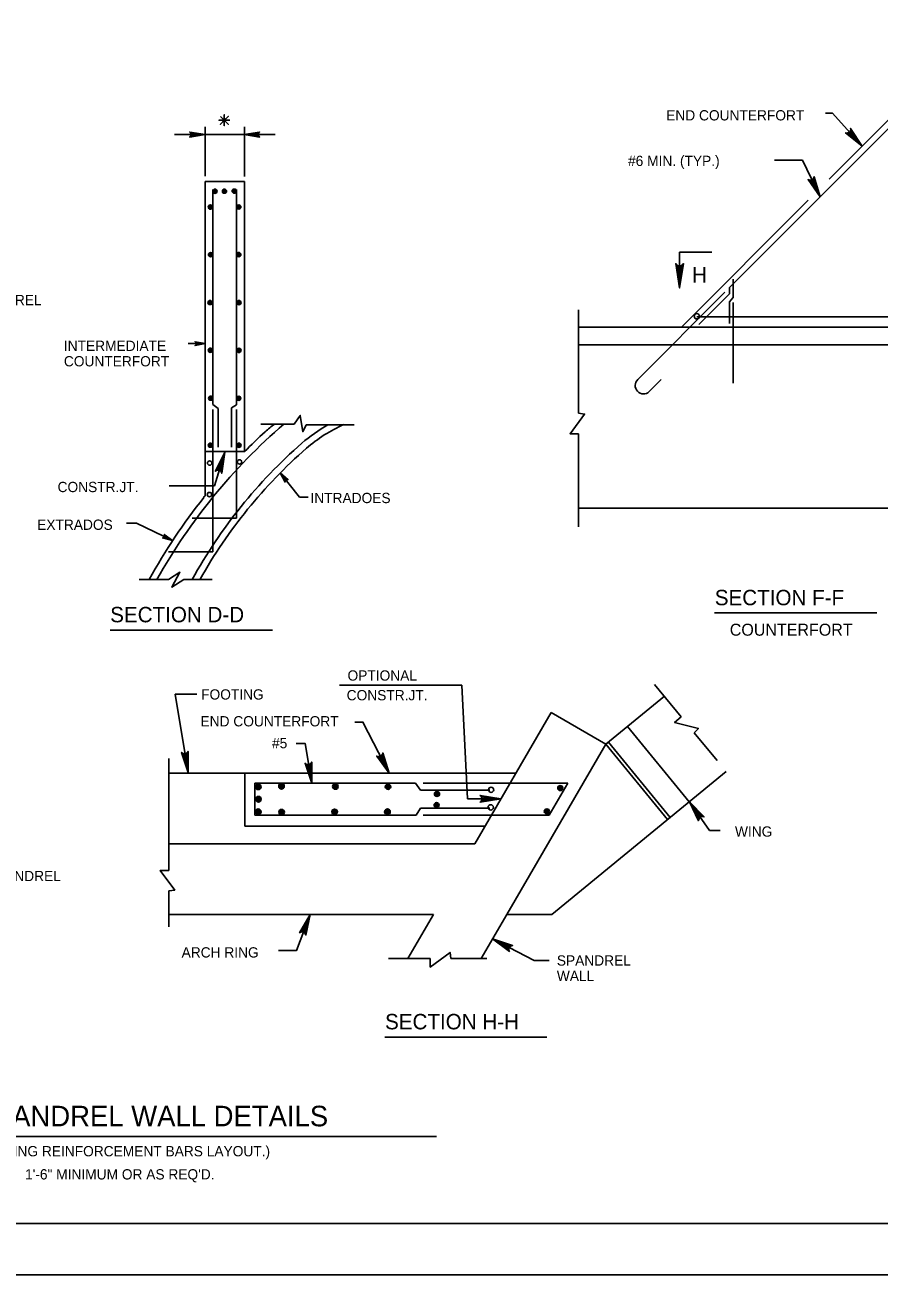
# Model space of a CAD drawing. Extents: x 639028 to 639883, y 298843 to 300031.
# Drawn here: x 639347.3 to 639596.7, y 298843.1 to 299207.9 of the extents above; entities that cross this region are included whole.
import ezdxf

# ---------------------------------------------------------------- set-up
doc = ezdxf.new("R2010")
doc.units = 0
for name, color, linetype in [('2', 7, 'Continuous'), ('52', 7, 'Continuous'), ('53', 7, 'Continuous'), ('PLT-BNDY', 7, 'Continuous')]:
    doc.layers.add(name, color=color, linetype=linetype)

msp = doc.modelspace()

# ---------------------------------------------------------------- linework, layer by layer
at = {"layer": '2'}
for p, q in [((639626.2, 299204.43), (639553.07, 299131.3)), ((639622.06, 299202.83), (639582.15, 299162.92)), ((639405.48, 299180.1), (639405.48, 299180.1)), ((639399.9, 299163.83), (639399.9, 299178.2)), ((639411.4, 299163.7), (639411.4, 299178.2)), ((639412.4, 299175.95), (639390.97, 299175.95)), ((639420.3, 299175.95), (639411.4, 299175.95)), ((639399.9, 299162.2), (639399.9, 299070.45)), ((639399.9, 299162.2), (639411.4, 299162.2)), ((639411.4, 299162.2), (639411.4, 299083.45)), ((639402.15, 299159.95), (639402.15, 299097.2)), ((639409.03, 299159.95), (639409.03, 299097.08)), ((639576.04, 299156.81), (639538.98, 299119.76)), ((639538.46, 299141.66), (639538.46, 299131.16)), ((639538.46, 299141.66), (639547.84, 299141.66)), ((639554.13, 299133.73), (639554.13, 299128.26)), ((639551.71, 299129.94), (639526.25, 299104.48)), ((639553.03, 299129.45), (639544.06, 299120.48)), ((639553.03, 299129.45), (639553.07, 299131.3)), ((639553.99, 299128.26), (639552.99, 299127.13)), ((639552.99, 299127.13), (639552.99, 299120.76)), ((639554.13, 299126.95), (639554.13, 299103.38)), ((639508.95, 299124.77), (639508.95, 299094.62)), ((639611.56, 299122.77), (639543.53, 299122.77)), ((639508.96, 299119.76), (639635.26, 299119.76)), ((639508.96, 299114.57), (639635.26, 299114.57)), ((639529.61, 299100.91), (639533.11, 299104.41)), ((639403.65, 299095.95), (639402.15, 299097.2)), ((639402.15, 299095.7), (639402.15, 299054.12)), ((639403.65, 299095.95), (639403.65, 299084.7)), ((639407.53, 299096.2), (639409.03, 299097.08)), ((639407.53, 299096.2), (639407.53, 299084.7)), ((639409.03, 299095.7), (639409.03, 299063.94)), ((639416.15, 299091.45), (639425.9, 299091.45)), ((639429.4, 299091.2), (639443.4, 299091.2)), ((639508.95, 299088.62), (639508.95, 299061.46)), ((639411.4, 299083.45), (639399.9, 299083.45)), ((639405.65, 299083.2), (639402.59, 299073.45)), ((639402.59, 299073.45), (639389.4, 299073.45)), ((639399.4, 299070.08), (639399.9, 299070.45)), ((639508.96, 299066.93), (639635.26, 299066.93)), ((639396.06, 299063.94), (639409.03, 299063.94)), ((639389.22, 299054.12), (639402.15, 299054.12)), ((639380.65, 299046.08), (639389.15, 299046.08)), ((639393.65, 299046.08), (639401.9, 299046.08)), ((639538.94, 299005.97), (639531.17, 299015.44)), ((639391.14, 299012.62), (639397.43, 299012.62)), ((639474.85, 299015.23), (639439.1, 299015.23)), ((639476.54, 298982.08), (639474.85, 299015.23)), ((639516.92, 298997.97), (639534.01, 299011.98)), ((639500.94, 299007.21), (639478.62, 298968.94)), ((639500.97, 299007.27), (639516.92, 298997.97)), ((639523.23, 299003.14), (639541.24, 298981.17)), ((639549.4, 298993.21), (639542.74, 299001.33)), ((639516.92, 298997.97), (639487.96, 298948.31)), ((639516.92, 298997.97), (639534.93, 298975.99)), ((639517.66, 298998.58), (639535.67, 298976.6)), ((639389.26, 298961.17), (639389.26, 298993.81)), ((639501.15, 298948.31), (639552.02, 298990)), ((639389.26, 298989.59), (639490.67, 298989.59)), ((639411.44, 298989.59), (639411.44, 298974.09)), ((639414.44, 298986.59), (639414.44, 298977.34)), ((639414.44, 298986.59), (639461.31, 298986.59)), ((639462.81, 298984.59), (639461.31, 298986.59)), ((639463.52, 298986.59), (639505.79, 298986.59)), ((639505.79, 298986.59), (639500.4, 298977.34)), ((639462.81, 298984.59), (639483.03, 298984.59)), ((639462.81, 298979.34), (639461.56, 298977.34)), ((639462.81, 298979.34), (639483.03, 298979.34)), ((639476.54, 298982.08), (639486.29, 298982.08)), ((639414.44, 298977.34), (639420.94, 298977.34)), ((639414.44, 298977.34), (639461.56, 298977.34)), ((639463.52, 298977.34), (639500.4, 298977.34)), ((639481.63, 298974.09), (639411.44, 298974.09)), ((639420.94, 298974.09), (639411.44, 298974.09)), ((639478.62, 298968.94), (639389.26, 298968.94)), ((639389.26, 298944.67), (639389.26, 298955.17)), ((639466.6, 298948.31), (639389.26, 298948.31)), ((639466.6, 298948.31), (639459.1, 298935.46)), ((639487.96, 298948.31), (639480.47, 298935.46)), ((639501.15, 298948.31), (639487.96, 298948.31)), ((639465.65, 298935.46), (639453.4, 298935.46)), ((639482.15, 298935.46), (639471.65, 298935.46)), ((639853.74, 298858.08), (639067.74, 298858.08))]:
    msp.add_line(p, q, dxfattribs=at)
for points in [[(639407.08, 299180.1), (639403.88, 299180.1), (639405.48, 299180.1), (639405.48, 299178.5), (639405.48, 299181.7), (639405.48, 299180.1), (639406.62, 299181.23), (639404.35, 299178.96), (639405.48, 299180.1), (639406.62, 299178.96), (639404.35, 299181.23)], [(639395.61, 299176.47), (639395.79, 299176.16), (639399.86, 299175.94), (639395.61, 299176.47), (639395.4, 299176.66), (639399.86, 299175.94), (639395.79, 299175.74), (639395.63, 299175.44), (639399.86, 299175.94), (639395.4, 299175.21), (639395.63, 299175.44)], [(639415.57, 299176.47), (639415.39, 299176.16), (639411.32, 299175.94), (639415.57, 299176.47), (639415.78, 299176.66), (639411.32, 299175.94), (639415.39, 299175.74), (639415.55, 299175.44), (639411.32, 299175.94), (639415.78, 299175.21), (639415.55, 299175.44)], [(639539.34, 299137.91), (639538.84, 299137.66), (639538.46, 299131.16), (639539.34, 299137.91), (639539.59, 299138.29), (639538.46, 299131.16), (639538.09, 299137.66), (639537.59, 299137.91), (639538.46, 299131.16), (639537.34, 299138.29), (639537.59, 299137.91)], [(639425.9, 299091.45), (639427.65, 299093.95), (639428.4, 299089.2), (639429.4, 299091.2)], [(639508.95, 299094.62), (639510.7, 299094.37), (639506.45, 299088.62), (639508.95, 299088.62)], [(639389.15, 299046.08), (639392.53, 299048.2), (639390.15, 299043.83), (639393.65, 299046.08)], [(639542.74, 299001.33), (639543.94, 299002.63), (639537, 299004.38), (639538.94, 299005.97)], [(639389.26, 298955.17), (639391.01, 298955.42), (639386.76, 298961.17), (639389.26, 298961.17)], [(639471.65, 298935.46), (639471.4, 298937.21), (639465.65, 298932.96), (639465.65, 298935.46)]]:
    msp.add_lwpolyline(points, dxfattribs=at)
for centre, radius in [((639402.75, 299159.4), 0.619), ((639402.75, 299159.39), 0.501), ((639402.75, 299159.39), 0.395), ((639402.75, 299159.38), 0.277), ((639402.75, 299159.4), 0.151), ((639402.76, 299159.39), 0.0427), ((639405.53, 299159.41), 0.619), ((639405.53, 299159.4), 0.501), ((639405.53, 299159.4), 0.395), ((639405.53, 299159.39), 0.277), ((639405.53, 299159.41), 0.151), ((639405.54, 299159.4), 0.0427), ((639408.39, 299159.43), 0.619), ((639408.39, 299159.43), 0.501), ((639408.39, 299159.43), 0.395), ((639408.39, 299159.41), 0.277), ((639408.39, 299159.44), 0.151), ((639408.4, 299159.43), 0.0427), ((639401.4, 299154.78), 0.619), ((639401.4, 299154.77), 0.501), ((639401.4, 299154.77), 0.395), ((639401.4, 299154.76), 0.277), ((639401.4, 299154.79), 0.151), ((639401.41, 299154.77), 0.0427), ((639409.69, 299154.81), 0.619), ((639409.7, 299154.8), 0.501), ((639409.7, 299154.8), 0.395), ((639409.7, 299154.79), 0.277), ((639409.7, 299154.81), 0.151), ((639409.71, 299154.8), 0.0427), ((639401.45, 299140.88), 0.619), ((639401.45, 299140.87), 0.501), ((639401.45, 299140.87), 0.395), ((639401.45, 299140.86), 0.277), ((639401.45, 299140.88), 0.151), ((639401.46, 299140.87), 0.0427), ((639409.69, 299140.91), 0.619), ((639409.7, 299140.9), 0.501), ((639409.7, 299140.9), 0.395), ((639409.7, 299140.89), 0.277), ((639409.7, 299140.91), 0.151), ((639409.71, 299140.9), 0.0427), ((639401.32, 299126.92), 0.619), ((639401.33, 299126.91), 0.501), ((639401.33, 299126.91), 0.395), ((639401.33, 299126.9), 0.277), ((639401.33, 299126.92), 0.151), ((639401.34, 299126.91), 0.0427), ((639409.74, 299126.89), 0.619), ((639409.74, 299126.88), 0.501), ((639409.74, 299126.88), 0.395), ((639409.74, 299126.87), 0.277), ((639409.74, 299126.89), 0.151), ((639409.75, 299126.88), 0.0427), ((639401.39, 299112.99), 0.619), ((639401.39, 299112.98), 0.501), ((639401.39, 299112.98), 0.395), ((639401.39, 299112.97), 0.277), ((639401.39, 299112.99), 0.151), ((639401.4, 299112.98), 0.0427), ((639409.74, 299112.95), 0.619), ((639409.74, 299112.94), 0.501), ((639409.74, 299112.94), 0.395), ((639409.74, 299112.93), 0.277), ((639409.74, 299112.96), 0.151), ((639409.75, 299112.94), 0.0427), ((639401.48, 299098.99), 0.619), ((639401.48, 299098.98), 0.501), ((639401.48, 299098.98), 0.395), ((639409.68, 299098.96), 0.619), ((639409.68, 299098.95), 0.501), ((639409.68, 299098.95), 0.395), ((639401.48, 299098.97), 0.277), ((639401.48, 299098.99), 0.151), ((639401.49, 299098.98), 0.0427), ((639409.68, 299098.94), 0.277), ((639409.68, 299098.96), 0.151), ((639409.69, 299098.95), 0.0427), ((639401.42, 299085.28), 0.619), ((639401.42, 299085.27), 0.501), ((639401.42, 299085.27), 0.395), ((639401.42, 299085.26), 0.277), ((639401.42, 299085.28), 0.151), ((639401.43, 299085.27), 0.0427), ((639409.77, 299085.25), 0.619), ((639409.77, 299085.24), 0.501), ((639409.77, 299085.24), 0.395), ((639409.77, 299085.23), 0.277), ((639409.77, 299085.25), 0.151), ((639409.79, 299085.24), 0.0427), ((639415.39, 298985.56), 0.825), ((639415.39, 298985.57), 0.668), ((639422.18, 298985.71), 0.825), ((639422.18, 298985.72), 0.668), ((639422.18, 298985.72), 0.527), ((639437.91, 298985.66), 0.825), ((639437.91, 298985.67), 0.668), ((639453.29, 298985.61), 0.825), ((639453.3, 298985.62), 0.668), ((639415.42, 298981.94), 0.825), ((639415.43, 298981.95), 0.668), ((639415.39, 298985.57), 0.527), ((639415.39, 298985.59), 0.37), ((639415.39, 298985.56), 0.202), ((639415.41, 298985.57), 0.0569), ((639422.18, 298985.73), 0.37), ((639422.18, 298985.7), 0.202), ((639422.2, 298985.72), 0.0569), ((639437.91, 298985.67), 0.527), ((639437.91, 298985.69), 0.37), ((639437.91, 298985.66), 0.202), ((639437.93, 298985.67), 0.0569), ((639453.3, 298985.62), 0.527), ((639453.3, 298985.63), 0.37), ((639453.3, 298985.61), 0.202), ((639453.31, 298985.62), 0.0569), ((639467.6, 298983.5), 0.75), ((639467.6, 298983.5), 0.563), ((639467.6, 298983.5), 0.375), ((639467.6, 298983.5), 0.188), ((639503.6, 298985.2), 0.75), ((639503.6, 298985.2), 0.563), ((639503.6, 298985.2), 0.375), ((639503.6, 298985.2), 0.188), ((639415.41, 298978.3), 0.825), ((639415.41, 298978.31), 0.668), ((639415.43, 298981.95), 0.527), ((639415.43, 298981.96), 0.37), ((639415.43, 298981.93), 0.202), ((639415.44, 298981.95), 0.0569), ((639422.23, 298978.16), 0.825), ((639437.71, 298978.22), 0.825), ((639453.14, 298978.31), 0.825), ((639453.15, 298978.33), 0.668), ((639467.48, 298980.21), 0.75), ((639467.48, 298980.21), 0.563), ((639467.48, 298980.21), 0.375), ((639467.48, 298980.21), 0.188), ((639499.7, 298978.38), 0.75), ((639415.41, 298978.31), 0.527), ((639415.41, 298978.32), 0.37), ((639415.41, 298978.3), 0.202), ((639415.42, 298978.31), 0.0569), ((639422.23, 298978.18), 0.668), ((639422.23, 298978.18), 0.527), ((639422.23, 298978.19), 0.37), ((639422.23, 298978.16), 0.202), ((639422.25, 298978.18), 0.0569), ((639437.72, 298978.23), 0.668), ((639437.72, 298978.23), 0.527), ((639437.72, 298978.24), 0.37), ((639437.72, 298978.21), 0.202), ((639437.73, 298978.23), 0.0569), ((639453.15, 298978.33), 0.527), ((639453.15, 298978.34), 0.37), ((639453.15, 298978.31), 0.202), ((639453.16, 298978.33), 0.0569), ((639499.7, 298978.38), 0.563), ((639499.7, 298978.38), 0.375), ((639499.7, 298978.38), 0.188)]:
    msp.add_circle(centre, radius, dxfattribs=at)
for centre, radius, start, end in [((639527.93, 299102.69), 2.45, 133.18, 313.18), ((639533.15, 298963.44), 168.95, 130.7372, 150.7163), ((639533.15, 298963.44), 170.93, 132.6358, 135.4203), ((639459.59, 299039.81), 64.97, 127.397, 130.5294), ((639459.59, 299049.09), 48.39, 119.5171, 130.5182), ((639459.59, 299049.09), 46.41, 114.388, 130.5182), ((639525.76, 298974.41), 148.16, 131.215, 151.0716), ((639525.76, 298974.41), 146.18, 131.215, 150.6112), ((639533.15, 298963.44), 170.93, 141.4339, 151.0783)]:
    msp.add_arc(centre, radius, start, end, dxfattribs=at)
at = {"layer": '52'}
msp.add_line((639394.94, 298989.75), (639391.14, 299012.62), dxfattribs=at)
for points in [[(639591.74, 299172.52), (639583.14, 299182.17), (639581.04, 299182.17)], [(639588.43, 299177.33), (639588.26, 299176.89), (639591.74, 299172.52), (639588.43, 299177.33), (639588.42, 299177.72), (639591.74, 299172.52), (639587.82, 299176.5), (639587.38, 299176.38), (639591.74, 299172.52), (639586.96, 299176.43), (639587.38, 299176.38)], [(639579.49, 299157.72), (639574.36, 299168.46), (639566.19, 299168.46)], [(639577.65, 299163.27), (639577.36, 299162.89), (639579.49, 299157.72), (639577.65, 299163.27), (639577.75, 299163.64), (639579.49, 299157.72), (639576.84, 299162.63), (639576.37, 299162.64), (639579.49, 299157.72), (639575.99, 299162.8), (639576.37, 299162.64)], [(639399.9, 299114.91), (639394.88, 299114.91)], [(639399.9, 299114.91), (639396.92, 299114.35), (639397.04, 299114.43), (639397.15, 299114.51), (639397.21, 299114.61), (639397.27, 299114.71), (639397.29, 299114.81), (639397.3, 299114.91), (639397.29, 299115.01), (639397.27, 299115.11), (639397.21, 299115.21), (639397.15, 299115.31), (639397.04, 299115.39), (639396.92, 299115.47), (639399.9, 299114.91), (639397.04, 299115.39), (639397.15, 299115.31), (639399.9, 299114.91), (639397.21, 299115.21), (639397.27, 299115.11), (639399.9, 299114.91), (639397.29, 299115.01), (639397.3, 299114.91), (639399.9, 299114.91), (639397.29, 299114.81), (639397.27, 299114.71), (639399.9, 299114.91), (639397.21, 299114.61), (639397.15, 299114.51), (639399.9, 299114.91), (639397.04, 299114.43)], [(639403.22, 299077.89), (639403.69, 299077.97), (639405.65, 299083.2), (639403.22, 299077.89), (639402.89, 299077.68), (639405.65, 299083.2), (639404.25, 299077.8), (639404.58, 299077.48), (639405.65, 299083.2), (639404.75, 299077.1), (639404.58, 299077.48)], [(639421.81, 299077.19), (639427.47, 299070.06), (639429.99, 299070.06)], [(639421.81, 299077.19), (639424.1, 299075.2), (639423.97, 299075.24), (639423.84, 299075.28), (639423.72, 299075.27), (639423.6, 299075.25), (639423.52, 299075.2), (639423.43, 299075.15), (639423.36, 299075.08), (639423.29, 299075), (639423.25, 299074.89), (639423.21, 299074.78), (639423.22, 299074.64), (639423.23, 299074.5), (639421.81, 299077.19), (639423.22, 299074.64), (639423.21, 299074.78), (639421.81, 299077.19), (639423.25, 299074.89), (639423.29, 299075), (639421.81, 299077.19), (639423.36, 299075.08), (639423.43, 299075.15), (639421.81, 299077.19), (639423.52, 299075.2), (639423.6, 299075.25), (639421.81, 299077.19), (639423.72, 299075.27), (639423.84, 299075.28), (639421.81, 299077.19), (639423.97, 299075.24)], [(639390.38, 299057.44), (639379.84, 299062.5), (639376.9, 299062.5)], [(639390.38, 299057.44), (639387.45, 299058.22), (639387.59, 299058.25), (639387.73, 299058.27), (639387.83, 299058.33), (639387.92, 299058.4), (639387.98, 299058.48), (639388.04, 299058.56), (639388.07, 299058.66), (639388.1, 299058.76), (639388.09, 299058.87), (639388.08, 299058.99), (639388.01, 299059.11), (639387.94, 299059.23), (639390.38, 299057.44), (639388.01, 299059.11), (639388.08, 299058.99), (639390.38, 299057.44), (639388.09, 299058.87), (639388.1, 299058.76), (639390.38, 299057.44), (639388.07, 299058.66), (639388.04, 299058.56), (639390.38, 299057.44), (639387.98, 299058.48), (639387.92, 299058.4), (639390.38, 299057.44), (639387.83, 299058.33), (639387.73, 299058.27), (639390.38, 299057.44), (639387.59, 299058.25)], [(639453.67, 298989.59), (639445.97, 299004.44), (639443.64, 299004.44)], [(639431.04, 298986.59), (639429.11, 298998.2), (639426.45, 298998.2)], [(639394.71, 298995.59), (639394.33, 298995.31), (639394.94, 298989.75), (639394.71, 298995.59), (639394.91, 298995.92), (639394.94, 298989.75), (639393.75, 298995.21), (639393.31, 298995.34), (639394.94, 298989.75), (639392.98, 298995.6), (639393.31, 298995.34)], [(639451.65, 298995.08), (639451.37, 298994.69), (639453.67, 298989.59), (639451.65, 298995.08), (639451.74, 298995.46), (639453.67, 298989.59), (639450.86, 298994.42), (639450.4, 298994.41), (639453.67, 298989.59), (639450, 298994.56), (639450.4, 298994.41)], [(639430.8, 298992.43), (639430.42, 298992.15), (639431.04, 298986.59), (639430.8, 298992.43), (639431, 298992.77), (639431.04, 298986.59), (639429.85, 298992.05), (639429.41, 298992.18), (639431.04, 298986.59), (639429.08, 298992.45), (639429.41, 298992.18)], [(639480.49, 298982.81), (639480.71, 298982.39), (639486.29, 298982.08), (639480.49, 298982.81), (639480.19, 298983.07), (639486.29, 298982.08), (639480.71, 298981.81), (639480.51, 298981.39), (639486.29, 298982.08), (639480.19, 298981.12), (639480.51, 298981.39)], [(639541.31, 298981.23), (639547.23, 298972.79), (639550.36, 298972.79)], [(639544.04, 298976.06), (639544.26, 298976.48), (639541.31, 298981.23), (639544.04, 298976.06), (639544.01, 298975.67), (639541.31, 298981.23), (639544.74, 298976.82), (639545.2, 298976.89), (639541.31, 298981.23), (639545.6, 298976.79), (639545.2, 298976.89)], [(639430.53, 298948.31), (639426.56, 298937.78), (639421.26, 298937.78)], [(639427.81, 298943.14), (639428.28, 298943.2), (639430.53, 298948.31), (639427.81, 298943.14), (639427.46, 298942.95), (639430.53, 298948.31), (639428.82, 298942.99), (639429.14, 298942.66), (639430.53, 298948.31), (639429.29, 298942.27), (639429.14, 298942.66)], [(639483.81, 298941.19), (639495.99, 298934.84), (639500.33, 298934.84)], [(639488.61, 298937.86), (639488.62, 298938.33), (639483.81, 298941.19), (639488.61, 298937.86), (639488.76, 298937.5), (639483.81, 298941.19), (639488.88, 298938.85), (639489.26, 298939.13), (639483.81, 298941.19), (639489.66, 298939.23), (639489.26, 298939.13)]]:
    msp.add_lwpolyline(points, dxfattribs=at)
for centre, radius in [((639543.5, 299122.9), 0.771), ((639401.2, 299080.06), 0.637), ((639409.92, 299080.4), 0.637), ((639401.14, 299070.88), 0.637), ((639483.41, 298984.7), 0.771), ((639483.3, 298979.57), 0.771)]:
    msp.add_circle(centre, radius, dxfattribs=at)
at = {"layer": '53'}
for p, q in [((639548.65, 299036.31), (639596.03, 299036.31)), ((639372.15, 299031.33), (639419.56, 299031.33)), ((639452.33, 298912.53), (639499.7, 298912.53)), ((639297.14, 298883.47), (639467.45, 298883.47))]:
    msp.add_line(p, q, dxfattribs=at)
at = {"layer": 'PLT-BNDY'}
msp.add_lwpolyline([(639027.74, 299437.08), (639868.74, 299437.08), (639868.74, 298843.08), (639027.74, 298843.08)], close=True, dxfattribs=at)

# ---------------------------------------------------------------- texts
at = {"layer": '2'}
for s, height, p in [('END COUNTERFORT', 3, (639534.55, 299180.06)), ('#6 MIN. (TYP.)', 3, (639523.41, 299166.77)), ('H', 4.5, (639542.08, 299132.76)), ('SPANDREL', 3, (639330.49, 299126.14)), ('INTERMEDIATE', 3, (639358.62, 299112.78)), ('COUNTERFORT', 3, (639358.62, 299108.28)), ('CONSTR.JT.', 3, (639356.78, 299071.58)), ('INTRADOES', 3, (639430.64, 299068.37)), ('EXTRADOS', 3, (639350.82, 299060.57)), ('OPTIONAL', 3, (639441.47, 299016.56)), ('FOOTING', 3, (639398.71, 299011.03)), ('CONSTR.JT.', 3, (639441.22, 299010.81)), ('END COUNTERFORT', 3, (639398.53, 299003.2)), ('#5', 3, (639419.41, 298996.82)), ('WING', 3, (639554.64, 298971.01)), ('SPANDREL', 3, (639336.11, 298958.03)), ('ARCH RING', 3, (639393.01, 298935.74)), ('SPANDREL', 3, (639502.61, 298933.38)), ('WALL', 3, (639502.61, 298928.88)), ('(SHOWING REINFORCEMENT BARS LAYOUT.)', 3, (639330.14, 298877.72)), ('1\'-6" MINIMUM OR AS REQ\'D.', 3, (639347.28, 298870.96))]:
    msp.add_text(s, height=height, dxfattribs=at).set_placement(p)
at = {"layer": '53'}
for s, height, p in [('SECTION F-F', 4.5, (639548.74, 299038.56)), ('SECTION D-D', 4.5, (639372.15, 299033.58)), ('COUNTERFORT', 3.5, (639553.12, 299029.67)), ('SECTION H-H', 4.5, (639452.43, 298914.78)), ('TYPICAL SPANDREL WALL DETAILS', 6, (639297.14, 298886.47))]:
    msp.add_text(s, height=height, dxfattribs=at).set_placement(p)

doc.saveas('drawing.dxf')
